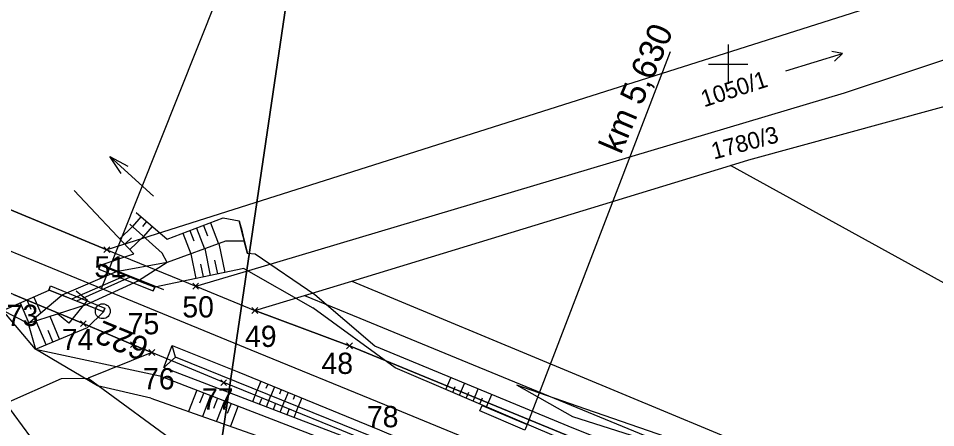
# Model space of a CAD drawing. Extents: x -779302 to -774398, y -1144902 to -1142831.
# Drawn here: x -775872.2 to -775778.9, y -1144336.9 to -1144295.3 of the extents above; entities that cross this region are included whole.
import ezdxf

# ---------------------------------------------------------------- set-up
doc = ezdxf.new("R2010")
doc.units = 0
for name, color, linetype in [('hektosit - Vrstva 5', 7, 'Continuous'), ('Hranice parcel', 7, 'Continuous'), ('legenda I_5_2 - Vrstva 53', 7, 'Continuous'), ('Parcelní čísla', 7, 'Continuous'), ('SŽDC', 7, 'Continuous'), ('Vrstva 1', 7, 'Continuous'), ('zjednodus_g_situ-seda - Vrstva 1', 7, 'Continuous'), ('zjednodus_g_situ-seda - Vrstva 13', 7, 'Continuous'), ('zjednodus_g_situ-seda - Vrstva 19', 7, 'Continuous'), ('zjednodus_g_situ-seda - Vrstva 36', 7, 'Continuous'), ('zjednodus_g_situ-seda - Vrstva 43', 7, 'Continuous'), ('zjednodus_g_situ-seda - Vrstva 48', 7, 'Continuous'), ('zjednodus_g_situ-seda - Vrstva 49', 7, 'Continuous'), ('zjednodus_g_situ-seda - Vrstva 63', 7, 'Continuous'), ('zjednodus_g_situ-seda - Vrstva 9', 7, 'Continuous'), ('Značky kultur', 7, 'Continuous')]:
    doc.layers.add(name, color=color, linetype=linetype)

msp = doc.modelspace()

# ---------------------------------------------------------------- linework, layer by layer
at = {"layer": 'hektosit - Vrstva 5'}
for p, q in [((-775800, -1144298), (-775800, -1144302)), ((-775802, -1144300), (-775798, -1144300))]:
    msp.add_line(p, q, dxfattribs=at)
at = {"layer": 'Hranice parcel'}
for p, q in [((-775838.28, -1144322.04), (-775799.75, -1144310.3)), ((-775863.23, -1144318.85), (-775854.19, -1144322.57)), ((-775854.19, -1144322.57), (-775848.16, -1144325.04)), ((-775843.11, -1144323.51), (-775838.28, -1144322.04)), ((-775848.16, -1144325.04), (-775843.11, -1144323.51)), ((-775858.65, -1144329.3), (-775865.13, -1144331.92)), ((-775865.13, -1144331.92), (-775851.83, -1144341.63))]:
    msp.add_line(p, q, dxfattribs=at)
for points in [[(-775854.19, -1144322.57), (-775847.52, -1144320.58), (-775788.13, -1144302.89), (-775641, -1144254.13), (-775572.06, -1144240.51), (-775529.27, -1144232.36), (-775512.82, -1144230.54), (-775459.3, -1144219.85)], [(-775863.23, -1144318.85), (-775876.16, -1144313.52), (-775955.63, -1144280.49)], [(-775784.72, -1144293.94), (-775787.46, -1144294.84), (-775863.23, -1144318.85)], [(-775799.75, -1144310.3), (-775797.87, -1144309.73), (-775773.94, -1144303.16)], [(-775535.75, -1144423.8), (-775563.71, -1144412.12), (-775608.65, -1144392.86), (-775648.34, -1144376.34), (-775671.65, -1144367.58), (-775726.63, -1144346.28), (-775769.26, -1144327.07), (-775799.75, -1144310.3)], [(-775838.28, -1144322.04), (-775792.62, -1144341.02), (-775687.59, -1144385.81), (-775625.87, -1144410.3)], [(-775872.73, -1144323.39), (-775865.63, -1144326.37), (-775860.54, -1144328.51), (-775858.65, -1144329.3)], [(-775843.11, -1144323.51), (-775837.49, -1144325.82), (-775689.36, -1144386.71), (-775625.87, -1144410.3)], [(-775474.88, -1144449.28), (-775529.11, -1144439.07), (-775574.03, -1144428.55), (-775626.91, -1144413.11), (-775690.5, -1144389.48), (-775838.53, -1144328.62), (-775848.16, -1144325.04)], [(-775839.31, -1144337.25), (-775851.34, -1144332.37), (-775858.65, -1144329.3)], [(-775873.53, -1144334.45), (-775867.86, -1144331.94), (-775865.13, -1144331.92)], [(-775568.49, -1144467.61), (-775658.94, -1144429.99), (-775756.48, -1144393.32), (-775816, -1144369.47), (-775857.28, -1144347.72), (-775870.12, -1144339.07), (-775873.53, -1144334.45)]]:
    msp.add_lwpolyline(points, dxfattribs=at)
at = {"layer": 'legenda I_5_2 - Vrstva 53'}
for points in [[(-776052.08, -1144238.11), (-776022.68, -1144250.27), (-776023.78, -1144252.86), (-775962.18, -1144277.9), (-775959.79, -1144278.81), (-775958.42, -1144279.33), (-775955.63, -1144280.49), (-775876.16, -1144313.52), (-775863.23, -1144318.85), (-775854.19, -1144322.57), (-775848.16, -1144325.04), (-775838.53, -1144328.62), (-775690.5, -1144389.48), (-775626.91, -1144413.11), (-775574.03, -1144428.55), (-775529.11, -1144439.07), (-775474.88, -1144449.28), (-775426.17, -1144455.72)], [(-775655.04, -1144411.89), (-775699.86, -1144394.42), (-775786.82, -1144358.72), (-775824.31, -1144343.39), (-775839.31, -1144337.25), (-775851.34, -1144332.37), (-775858.65, -1144329.3), (-775860.54, -1144328.51), (-775865.63, -1144326.37), (-775872.73, -1144323.39), (-775879.1, -1144320.81), (-775959.71, -1144287.76), (-775961.16, -1144287.17), (-775962.59, -1144286.8), (-775964.09, -1144286.42), (-775971.84, -1144282.92), (-776064.26, -1144245.03)]]:
    msp.add_lwpolyline(points, dxfattribs=at)
at = {"layer": 'SŽDC'}
for p, q in [((-775863.03, -1144319.05), (-775863.53, -1144318.55)), ((-775863.03, -1144318.65), (-775863.53, -1144319.15)), ((-775863.43, -1144319.05), (-775862.93, -1144318.55)), ((-775863.43, -1144318.65), (-775862.93, -1144319.15)), ((-775863.23, -1144318.85), (-775863.23, -1144318.85)), ((-775853.99, -1144322.77), (-775854.49, -1144322.27)), ((-775853.99, -1144322.37), (-775854.49, -1144322.87)), ((-775854.39, -1144322.77), (-775853.89, -1144322.27)), ((-775854.39, -1144322.37), (-775853.89, -1144322.87)), ((-775854.19, -1144322.57), (-775854.19, -1144322.57)), ((-775847.96, -1144325.24), (-775848.46, -1144324.74)), ((-775847.96, -1144324.84), (-775848.46, -1144325.34)), ((-775848.36, -1144325.24), (-775847.86, -1144324.74)), ((-775848.36, -1144324.84), (-775847.86, -1144325.34)), ((-775848.16, -1144325.04), (-775848.16, -1144325.04)), ((-775865.43, -1144326.57), (-775865.93, -1144326.07)), ((-775865.43, -1144326.17), (-775865.93, -1144326.67)), ((-775865.83, -1144326.57), (-775865.33, -1144326.07)), ((-775865.83, -1144326.17), (-775865.33, -1144326.67)), ((-775865.63, -1144326.37), (-775865.63, -1144326.37)), ((-775860.34, -1144328.71), (-775860.84, -1144328.21)), ((-775860.34, -1144328.31), (-775860.84, -1144328.81)), ((-775860.74, -1144328.71), (-775860.24, -1144328.21)), ((-775860.74, -1144328.31), (-775860.24, -1144328.81)), ((-775860.54, -1144328.51), (-775860.54, -1144328.51)), ((-775858.45, -1144329.5), (-775858.95, -1144329)), ((-775858.45, -1144329.1), (-775858.95, -1144329.6)), ((-775858.85, -1144329.5), (-775858.35, -1144329)), ((-775858.85, -1144329.1), (-775858.35, -1144329.6)), ((-775838.33, -1144328.82), (-775838.83, -1144328.32)), ((-775838.33, -1144328.42), (-775838.83, -1144328.92)), ((-775838.73, -1144328.82), (-775838.23, -1144328.32)), ((-775838.73, -1144328.42), (-775838.23, -1144328.92)), ((-775838.53, -1144328.62), (-775838.53, -1144328.62)), ((-775858.65, -1144329.3), (-775858.65, -1144329.3)), ((-775851.14, -1144332.57), (-775851.64, -1144332.07)), ((-775851.14, -1144332.17), (-775851.64, -1144332.67)), ((-775851.54, -1144332.57), (-775851.04, -1144332.07)), ((-775851.54, -1144332.17), (-775851.04, -1144332.67)), ((-775851.34, -1144332.37), (-775851.34, -1144332.37))]:
    msp.add_line(p, q, dxfattribs=at)
for points in [[(-776052.08, -1144238.11), (-776022.68, -1144250.27), (-776023.78, -1144252.86), (-775962.18, -1144277.9), (-775959.79, -1144278.81), (-775958.42, -1144279.33), (-775955.63, -1144280.49), (-775876.16, -1144313.52), (-775863.23, -1144318.85), (-775854.19, -1144322.57), (-775848.16, -1144325.04), (-775838.53, -1144328.62), (-775690.5, -1144389.48), (-775626.91, -1144413.11), (-775574.03, -1144428.55), (-775529.11, -1144439.07), (-775474.88, -1144449.28), (-775426.17, -1144455.72)], [(-775655.04, -1144411.89), (-775699.86, -1144394.42), (-775786.82, -1144358.72), (-775824.31, -1144343.39), (-775839.31, -1144337.25), (-775851.34, -1144332.37), (-775858.65, -1144329.3), (-775860.54, -1144328.51), (-775865.63, -1144326.37), (-775872.73, -1144323.39), (-775879.1, -1144320.81), (-775959.71, -1144287.76), (-775961.16, -1144287.17), (-775962.59, -1144286.8), (-775964.09, -1144286.42), (-775971.84, -1144282.92), (-776064.26, -1144245.03)]]:
    msp.add_lwpolyline(points, dxfattribs=at)
at = {"layer": 'Vrstva 1'}
for points in [[(-774810.638, -1144374.46), (-775834.484, -1144222.921), (-775875.041, -1144496.936), (-774851.195, -1144648.475)], [(-774851.195, -1144648.475), (-775875.041, -1144496.936), (-775834.484, -1144222.921), (-774810.638, -1144374.46)]]:
    msp.add_lwpolyline(points, close=True, dxfattribs=at)
at = {"layer": 'zjednodus_g_situ-seda - Vrstva 1'}
msp.add_lwpolyline([(-775727.95, -1144378.482), (-775748.85, -1144369.928), (-775769.932, -1144361.277), (-775794.144, -1144351.36), (-775818.196, -1144341.502), (-775834.949, -1144334.628), (-775848.538, -1144329.06), (-775863.633, -1144322.873), (-775881.696, -1144315.461), (-775900.226, -1144307.863), (-775924.104, -1144298.074), (-775945.912, -1144289.136), (-775969.086, -1144279.638), (-775991.271, -1144270.548), (-776009.963, -1144262.881), (-776026.16, -1144256.243), (-776044.897, -1144248.56), (-776062.233, -1144241.452)], dxfattribs=at)
at = {"layer": 'zjednodus_g_situ-seda - Vrstva 13'}
for p, q in [((-775858.478, -1144313.417), (-775862.923, -1144309.387)), ((-775857.594, -1144319.2), (-775860.89, -1144316.246))]:
    msp.add_line(p, q, dxfattribs=at)
msp.add_lwpolyline([(-775861.777, -1144311.1), (-775862.923, -1144309.387), (-775861.105, -1144310.36)], dxfattribs=at)
at = {"layer": 'zjednodus_g_situ-seda - Vrstva 19'}
for p, q in [((-775863.793, -1144322.807), (-775837.531, -1144257.035)), ((-775862.272, -1144321.114), (-775867.803, -1144323.466)), ((-775861.311, -1144321.474), (-775866.836, -1144323.868)), ((-775864.058, -1144320.825), (-775858.531, -1144323.023)), ((-775869.12, -1144322.982), (-775868.986, -1144322.538)), ((-775860.857, -1144321.654), (-775866.324, -1144324.082)), ((-775859.999, -1144322.028), (-775865.339, -1144324.461)), ((-775863.592, -1144325.163), (-775863.437, -1144324.781))]:
    msp.add_line(p, q, dxfattribs=at)
for points in [[(-775848.926, -1144319.237), (-775849.777, -1144315.929), (-775849.769, -1144315.934), (-775849.509, -1144316.864), (-775849.27, -1144317.982), (-775848.928, -1144319.237), (-775848.926, -1144319.237)], [(-775864.058, -1144320.825), (-775863.925, -1144320.436), (-775863.924, -1144320.437)], [(-775858.366, -1144322.648), (-775863.924, -1144320.437), (-775864.058, -1144320.825)], [(-775858.365, -1144322.65), (-775859.999, -1144322.028), (-775859.994, -1144322.029), (-775860.855, -1144321.656), (-775860.857, -1144321.654), (-775861.311, -1144321.474), (-775861.312, -1144321.473), (-775862.264, -1144321.117), (-775862.272, -1144321.114), (-775863.925, -1144320.436)], [(-775863.437, -1144324.781), (-775863.592, -1144325.164), (-775869.131, -1144322.953), (-775868.986, -1144322.538), (-775863.437, -1144324.781)], [(-775863.592, -1144325.164), (-775863.592, -1144325.163), (-775865.339, -1144324.461), (-775865.331, -1144324.458), (-775866.312, -1144324.091), (-775866.324, -1144324.082), (-775866.836, -1144323.868), (-775866.831, -1144323.869), (-775867.796, -1144323.467), (-775867.803, -1144323.466), (-775869.12, -1144322.982), (-775869.131, -1144322.953)], [(-775858.531, -1144323.023), (-775858.366, -1144322.648), (-775858.365, -1144322.65), (-775858.531, -1144323.023)]]:
    msp.add_lwpolyline(points, dxfattribs=at)
at = {"layer": 'zjednodus_g_situ-seda - Vrstva 36'}
msp.add_line((-775857.431, -1144322.917), (-775863.961, -1144320.311), dxfattribs=at)
at = {"layer": 'zjednodus_g_situ-seda - Vrstva 43'}
msp.add_lwpolyline([(-775866.368, -1144323.049), (-775865.206, -1144323.998), (-775867.104, -1144326.322), (-775868.266, -1144325.373)], dxfattribs=at)
at = {"layer": 'zjednodus_g_situ-seda - Vrstva 48'}
for p, q in [((-775859.759, -1144315.507), (-775860.611, -1144316.496)), ((-775859.191, -1144315.997), (-775859.622, -1144316.496)), ((-775861.925, -1144317.746), (-775860.608, -1144316.498)), ((-775858.623, -1144316.486), (-775859.494, -1144317.497)), ((-775854.797, -1144316.912), (-775854.395, -1144317.965)), ((-775854.097, -1144316.645), (-775853.289, -1144318.761)), ((-775853.396, -1144316.377), (-775852.99, -1144317.44)), ((-775852.695, -1144316.11), (-775851.88, -1144318.245)), ((-775861.409, -1144318.29), (-775860.729, -1144317.645)), ((-775860.894, -1144318.835), (-775859.488, -1144317.503)), ((-775855.498, -1144317.18), (-775854.697, -1144319.277)), ((-775852.676, -1144321.474), (-775853.241, -1144318.743)), ((-775851.207, -1144321.17), (-775851.817, -1144318.222)), ((-775854.145, -1144321.777), (-775854.665, -1144319.265)), ((-775853.411, -1144321.626), (-775853.682, -1144320.315)), ((-775851.942, -1144321.322), (-775852.235, -1144319.902)), ((-775872.058, -1144324.263), (-775871.168, -1144326.305)), ((-775871.37, -1144323.963), (-775870.97, -1144324.882)), ((-775870.683, -1144323.663), (-775869.971, -1144325.296)), ((-775869.427, -1144328.522), (-775870.425, -1144326.105)), ((-775868.04, -1144327.949), (-775868.993, -1144325.642)), ((-775868.734, -1144328.236), (-775869.221, -1144327.055)), ((-775828.716, -1144333.066), (-775828.204, -1144331.869)), ((-775847.556, -1144332.224), (-775847.929, -1144333.136)), ((-775846.862, -1144332.508), (-775847.048, -1144332.962)), ((-775846.168, -1144332.792), (-775846.538, -1144333.696)), ((-775828.027, -1144333.36), (-775827.769, -1144332.758)), ((-775827.337, -1144333.655), (-775826.818, -1144332.442)), ((-775854.073, -1144333.125), (-775854.91, -1144335.297)), ((-775853.373, -1144333.395), (-775853.787, -1144334.471)), ((-775852.673, -1144333.665), (-775853.494, -1144335.796)), ((-775848.382, -1144334.291), (-775847.939, -1144333.132)), ((-775846.981, -1144334.826), (-775846.548, -1144333.692)), ((-775845.474, -1144333.076), (-775845.658, -1144333.526)), ((-775844.78, -1144333.36), (-775845.147, -1144334.257)), ((-775844.085, -1144333.644), (-775844.268, -1144334.09)), ((-775826.647, -1144333.95), (-775826.386, -1144333.34)), ((-775825.958, -1144334.245), (-775825.432, -1144333.015)), ((-775824.579, -1144334.835), (-775824.046, -1144333.589)), ((-775851.973, -1144333.934), (-775852.38, -1144334.99)), ((-775851.273, -1144334.204), (-775852.079, -1144336.294)), ((-775850.573, -1144334.474), (-775850.972, -1144335.509)), ((-775847.682, -1144334.558), (-775847.463, -1144333.985)), ((-775846.281, -1144335.094), (-775846.066, -1144334.533)), ((-775845.58, -1144335.362), (-775845.156, -1144334.253)), ((-775843.391, -1144333.928), (-775843.755, -1144334.817)), ((-775825.268, -1144334.54), (-775825.003, -1144333.921)), ((-775849.874, -1144334.743), (-775850.663, -1144336.793)), ((-775844.88, -1144335.63), (-775844.67, -1144335.082)), ((-775844.179, -1144335.898), (-775843.765, -1144334.814))]:
    msp.add_line(p, q, dxfattribs=at)
at = {"layer": 'zjednodus_g_situ-seda - Vrstva 49'}
for p, q in [((-775849.283, -1144320.772), (-775842.27, -1144324.752)), ((-775871.246, -1144326.371), (-775873.833, -1144325.037)), ((-775871.246, -1144326.371), (-775870.5, -1144328.965)), ((-775870.5, -1144328.965), (-775857.833, -1144331.676)), ((-775856.259, -1144329.78), (-775856.585, -1144328.608)), ((-775856.259, -1144329.78), (-775857.427, -1144330.833)), ((-775857.427, -1144330.833), (-775835.896, -1144339.064)), ((-775857.833, -1144331.676), (-775836.223, -1144340.004)), ((-775858.751, -1144333.944), (-775837.785, -1144341.329))]:
    msp.add_line(p, q, dxfattribs=at)
for points in [[(-775849.283, -1144320.772), (-775858.365, -1144322.65), (-775858.366, -1144322.648), (-775863.924, -1144320.437), (-775863.925, -1144320.436), (-775860.473, -1144319.279), (-775866.568, -1144312.844)], [(-775860.248, -1144315.085), (-775857.106, -1144317.794), (-775851.403, -1144315.616), (-775849.777, -1144315.929), (-775848.926, -1144319.237), (-775848.928, -1144319.237)], [(-775857.09, -1144320.153), (-775857.594, -1144319.2), (-775860.89, -1144316.246)], [(-775842.069, -1144323.424), (-775848.143, -1144319.295), (-775848.928, -1144319.237), (-775849.27, -1144317.982), (-775851.149, -1144317.977), (-775857.09, -1144320.153), (-775859.999, -1144322.028), (-775858.365, -1144322.65)], [(-775857.09, -1144320.153), (-775862.272, -1144321.114), (-775863.925, -1144320.436)], [(-775870.5, -1144328.965), (-775873.833, -1144325.037), (-775869.12, -1144322.982)], [(-775863.592, -1144325.163), (-775865.339, -1144324.461), (-775871.246, -1144326.371), (-775867.803, -1144323.466), (-775869.12, -1144322.982)], [(-775863.592, -1144325.163), (-775863.592, -1144325.164), (-775869.131, -1144322.953), (-775869.12, -1144322.982)], [(-775688.651, -1144389.551), (-775696.633, -1144386.053), (-775726.898, -1144372.596), (-775749.273, -1144363.776), (-775768.84, -1144355.653), (-775791.984, -1144346.428), (-775815.704, -1144337.037), (-775835.953, -1144328.666), (-775842.069, -1144323.424)], [(-775870.5, -1144328.965), (-775865.203, -1144326.778), (-775863.592, -1144325.163)], [(-775688.651, -1144389.551), (-775697.111, -1144387.587), (-775726.524, -1144375.009), (-775750.249, -1144365.442), (-775769.82, -1144357.75), (-775792.578, -1144347.768), (-775815.796, -1144338.592), (-775833.87, -1144330.861), (-775842.27, -1144324.752)], [(-775858.751, -1144333.944), (-775864.177, -1144332.678), (-775870.5, -1144328.965)], [(-775857.427, -1144330.833), (-775856.585, -1144328.608), (-775849.791, -1144331.31), (-775835.471, -1144337.167), (-775819.067, -1144344.139), (-775794.874, -1144353.952), (-775771.011, -1144363.657), (-775749.958, -1144372.232), (-775728.756, -1144380.866), (-775705.088, -1144390.58), (-775688.995, -1144397.117), (-775677.109, -1144401.912), (-775676.986, -1144402.521)], [(-775676.986, -1144402.521), (-775689.361, -1144397.762), (-775705.135, -1144391.25), (-775728.991, -1144381.603), (-775750.394, -1144372.964), (-775772.924, -1144363.782), (-775795.386, -1144354.489), (-775819.108, -1144344.828), (-775836.017, -1144337.935), (-775856.259, -1144329.78)], [(-775688.651, -1144389.551), (-775696.098, -1144384.986), (-775725.347, -1144371.052), (-775748.187, -1144361.538), (-775768.169, -1144353.213), (-775790.951, -1144343.755), (-775815.805, -1144335.853), (-775821.491, -1144332.636)], [(-775688.651, -1144389.551), (-775695.69, -1144383.896), (-775725.101, -1144369.587), (-775747.724, -1144359.859), (-775767.79, -1144352.114), (-775790.924, -1144343.208), (-775815.356, -1144334.764), (-775821.491, -1144332.636)]]:
    msp.add_lwpolyline(points, dxfattribs=at)
at = {"layer": 'zjednodus_g_situ-seda - Vrstva 63'}
msp.add_line((-775863.6, -1144325.125), (-775863.692, -1144325.087), dxfattribs=at)
msp.add_circle((-775863.646, -1144325.106), 0.756, dxfattribs=at)
at = {"layer": 'zjednodus_g_situ-seda - Vrstva 9'}
msp.add_line((-775820.556, -1144336.916), (-775805.865, -1144298.709), dxfattribs=at)
msp.add_lwpolyline([(-775820.205, -1144336.087), (-775820.439, -1144336.64), (-775820.673, -1144337.192), (-775825.276, -1144335.24), (-775825.042, -1144334.688), (-775820.439, -1144336.64)], dxfattribs=at)
at = {"layer": 'Značky kultur'}
for p, q in [((-775794.102, -1144300.656), (-775788.364, -1144298.902)), ((-775788.364, -1144298.902), (-775789.445, -1144298.708)), ((-775788.364, -1144298.902), (-775789.152, -1144299.667))]:
    msp.add_line(p, q, dxfattribs=at)

# ---------------------------------------------------------------- texts
at = {"layer": 'Parcelní čísla'}
for s, rotation, p in [('1050/1', 18, (-775802.438, -1144304.381)), ('1780/3', 15, (-775801.444, -1144309.691))]:
    msp.add_text(s, height=1.7, rotation=rotation, dxfattribs=at).set_placement(p)
at = {"layer": 'SŽDC'}
for s, p in [('51', (-775864.503, -1144321.669)), ('73', (-775873.432, -1144326.604)), ('50', (-775855.551, -1144325.741)), ('75', (-775861.111, -1144327.452)), ('74', (-775867.826, -1144329.058)), ('49', (-775849.17, -1144328.738)), ('48', (-775841.384, -1144331.483)), ('76', (-775859.554, -1144333.054)), ('77', (-775853.548, -1144335.108)), ('78', (-775836.763, -1144336.906))]:
    msp.add_text(s, height=2.16, dxfattribs=at).set_placement(p)
at = {"layer": 'zjednodus_g_situ-seda - Vrstva 63'}
msp.add_text('622', height=2.4, rotation=157.71271, dxfattribs=at).set_placement((-775858.752, -1144328.015))
at = {"layer": 'zjednodus_g_situ-seda - Vrstva 9'}
msp.add_text('km 5,630', height=2.5, rotation=67.01759, dxfattribs=at).set_placement((-775810.905, -1144309.245))

doc.saveas('drawing.dxf')
